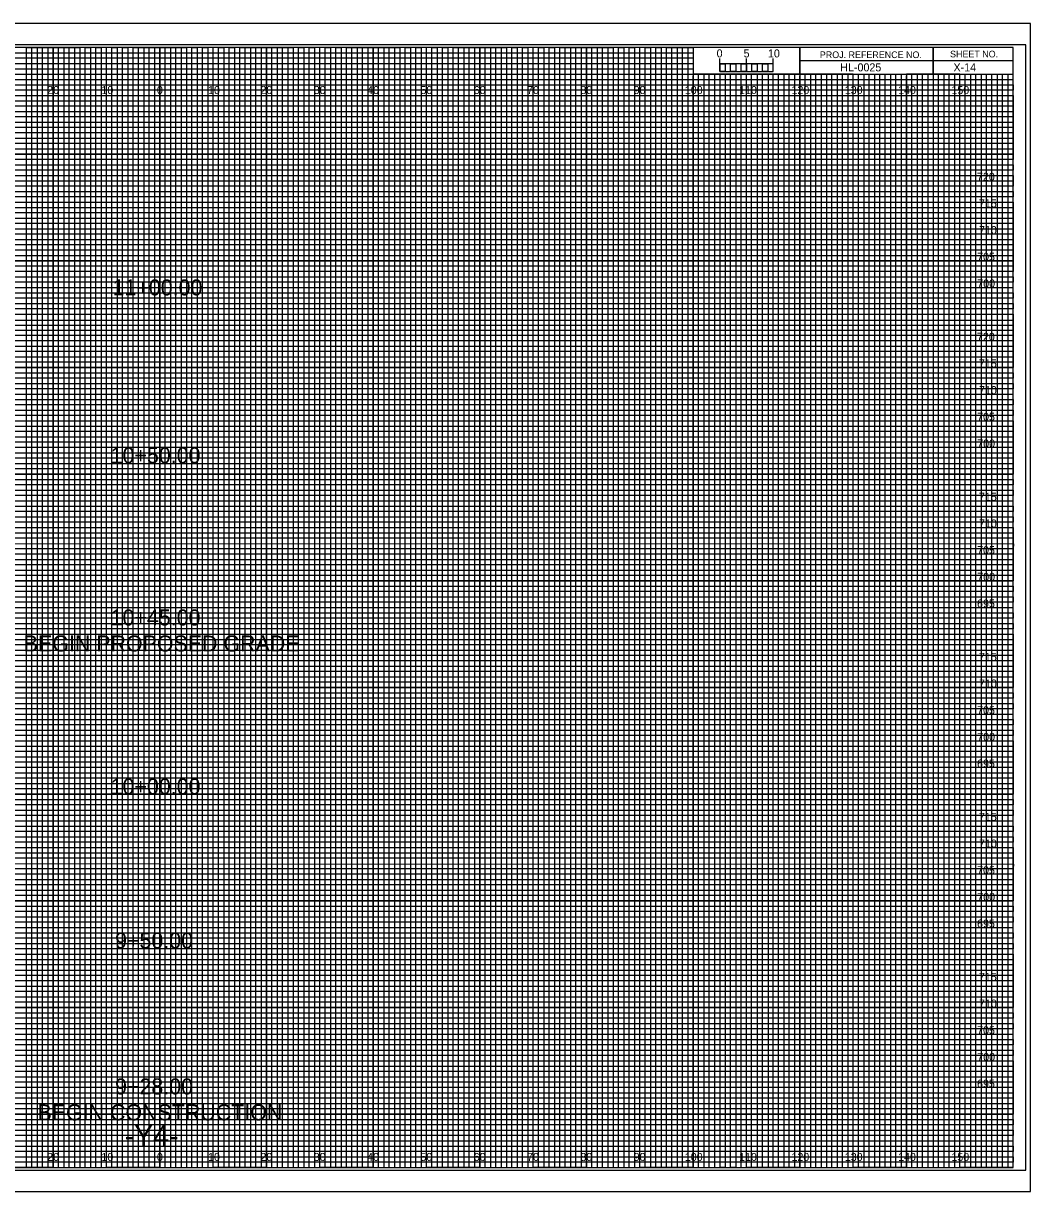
# Model space of a CAD drawing. Extents: x -13 to 323, y -5 to 434.
# Drawn here: x 134.4 to 323.3, y -4.5 to 214.5 of the extents above; entities that cross this region are included whole.
import ezdxf

# ---------------------------------------------------------------- set-up
doc = ezdxf.new("R2010")
doc.units = 0
for name, color, linetype in [('Exist CMT Pavement', 7, 'Continuous'), ('Exist Cross Section Cell', 7, 'Continuous'), ('Exist XS Center Line Elevation Label', 7, 'Continuous'), ('Exist XS Ground Line', 7, 'Continuous'), ('Prop CMT Pvmt Course 1 Wedge', 7, 'Continuous'), ('Prop CMT Pvmt Course 2', 7, 'Continuous'), ('Prop CMT Pvmt Course 3', 7, 'Continuous'), ('Prop CMT Pvmt Surface', 7, 'Continuous'), ('Prop CMT Pvmt Surface Shoulder', 7, 'Continuous'), ('Prop CMT Pvmt Wedge Surface 1', 7, 'Continuous'), ('Prop CMT Pvmt Wedge Surface 2', 7, 'Continuous'), ('Prop CMT Pvmt Wedge Surface 3', 7, 'Continuous'), ('Prop CMT Shld Paved Course 1', 7, 'Continuous'), ('Prop CMT Shld Paved Course 2', 7, 'Continuous'), ('Prop CMT Shld Paved Course 3', 7, 'Continuous'), ('Prop CMT Subgrade Earthwork', 7, 'Continuous'), ('Scratch_Level_1', 7, 'Continuous')]:
    doc.layers.add(name, color=color, linetype=linetype)

msp = doc.modelspace()

# ---------------------------------------------------------------- linework, layer by layer
at = {"layer": 'Exist XS Center Line Elevation Label'}
for points in [[(125, 0), (135, 0), (135, 210), (145, 210), (145, 0), (155, 0), (155, 210), (165, 210), (165, 0), (175, 0), (175, 210), (185, 210), (185, 0), (195, 0), (195, 210), (205, 210), (205, 0), (215, 0), (215, 210), (225, 210), (225, 0), (235, 0), (235, 210), (245, 210), (245, 0), (255, 0), (255, 210), (259.93, 210), (260, 210), (260, 205), (264.99, 205), (264.99, 0), (275, 0), (275, 205), (285, 205), (285, 0), (295, 0), (295, 205), (305, 205), (305, 0), (315, 0), (315, 205)], [(0, 205), (275, 205)], [(0, 185), (320, 185), (320, 195), (0, 195)], [(0, 165), (320, 165), (320, 175), (0, 175)], [(0, 145), (320, 145), (320, 155), (0, 155)], [(0, 125), (320, 125), (320, 135), (0, 135)], [(0, 105), (320, 105), (320, 115), (0, 115)], [(0, 85), (320, 85), (320, 95), (0, 95)], [(0, 65), (320, 65), (320, 75), (0, 75)], [(0, 45), (320, 45), (320, 55), (0, 55)], [(0, 25), (320, 25), (320, 35), (0, 35)], [(0, 5), (320, 5), (320, 15), (0, 15)]]:
    msp.add_lwpolyline(points, dxfattribs=at)
at = {"layer": 'Exist XS Ground Line'}
for p, q in [((150, 210), (140, 210)), ((140, 210), (140, 0)), ((150, 0), (150, 210)), ((170, 210), (160, 210)), ((160, 210), (160, 0)), ((170, 0), (170, 210)), ((190, 210), (180, 210)), ((180, 210), (180, 0)), ((190, 0), (190, 210)), ((210, 210), (200, 210)), ((200, 210), (200, 0)), ((210, 0), (210, 210)), ((230, 210), (220, 210)), ((220, 210), (220, 0)), ((230, 0), (230, 210)), ((250, 210), (240, 210)), ((240, 210), (240, 0)), ((250, 0), (250, 210)), ((260, 210), (260, 0)), ((270, 0), (270, 205)), ((290, 205), (280, 205)), ((280, 205), (280, 0)), ((290, 0), (290, 205)), ((310, 205), (300, 205)), ((300, 205), (300, 0)), ((310, 0), (310, 205)), ((140, 0), (130, 0)), ((160, 0), (150, 0)), ((180, 0), (170, 0)), ((200, 0), (190, 0)), ((220, 0), (210, 0)), ((240, 0), (230, 0)), ((260, 0), (250, 0)), ((280, 0), (270, 0)), ((300, 0), (290, 0)), ((320, 0), (310, 0)), ((320, 0), (320, 0))]:
    msp.add_line(p, q, dxfattribs=at)
for points in [[(0, 200), (320, 200), (320, 190), (0, 190)], [(0, 180), (320, 180), (320, 170), (0, 170)], [(0, 160), (320, 160), (320, 150), (0, 150)], [(0, 140), (320, 140), (320, 130), (0, 130)], [(0, 120), (320, 120), (320, 110), (0, 110)], [(0, 100), (320, 100), (320, 90), (0, 90)], [(0, 80), (320, 80), (320, 70), (0, 70)], [(0, 60), (320, 60), (320, 50), (0, 50)], [(0, 40), (320, 40), (320, 30), (0, 30)], [(0, 20), (320, 20), (320, 10), (0, 10)]]:
    msp.add_lwpolyline(points, dxfattribs=at)
at = {"layer": 'Prop CMT Pvmt Course 1 Wedge'}
for p, q in [((323.3, 214.5), (-13.4, 214.5)), ((-13.4, -4.5), (323.3, -4.5))]:
    msp.add_line(p, q, dxfattribs=at)
at = {"layer": 'Prop CMT Pvmt Course 2'}
msp.add_lwpolyline([(-13.4, -4.5), (323.3, -4.5), (323.3, 214.5), (-13.4, 214.5)], close=True, dxfattribs=at)
at = {"layer": 'Prop CMT Pvmt Course 3'}
msp.add_lwpolyline([(-10.8, -0.5), (322.4, -0.5), (322.4, 210.5), (-10.8, 210.5)], close=True, dxfattribs=at)
at = {"layer": 'Prop CMT Shld Paved Course 1'}
for p, q in [((305, 210), (305, 205)), ((305, 205), (305, 210)), ((280, 207.5), (280, 205)), ((320, 207.49), (280, 207.49)), ((280, 205), (320, 205))]:
    msp.add_line(p, q, dxfattribs=at)
for points in [[(320, 210), (0, 210), (0, 0), (320, 0)], [(280, 210), (260, 210), (260, 205.03), (280, 205.03)], [(320, 210), (280, 210), (280, 205), (320, 205)]]:
    msp.add_lwpolyline(points, close=True, dxfattribs=at)
at = {"layer": 'Prop CMT Shld Paved Course 2'}
for p, q in [((267, 205), (266.01, 205)), ((266.01, 205), (266.01, 0)), ((267, 0), (267, 205)), ((269, 205), (268, 205)), ((268, 205), (268, 0)), ((269, 0), (269, 205)), ((266.01, 0), (265, 0)), ((268, 0), (267, 0))]:
    msp.add_line(p, q, dxfattribs=at)
for points in [[(135, 0), (136, 0), (136, 210), (137, 210), (137, 0)], [(137, 0), (138, 0), (138, 210), (139, 210), (139, 0)], [(140, 0), (141, 0), (141, 210), (142, 210), (142, 0)], [(142, 0), (143, 0), (143, 210), (144, 210), (144, 0)], [(145, 0), (146, 0), (146, 210), (147, 210), (147, 0)], [(147, 0), (148, 0), (148, 210), (149, 210), (149, 0)], [(150, 0), (151, 0), (151, 210), (152, 210), (152, 0)], [(152, 0), (153, 0), (153, 210), (154, 210), (154, 0)], [(155, 0), (156, 0), (156, 210), (157, 210), (157, 0)], [(157, 0), (158, 0), (158, 210), (159, 210), (159, 0)], [(160, 0), (161, 0), (161, 210), (162, 210), (162, 0)], [(162, 0), (163, 0), (163, 210), (164, 210), (164, 0)], [(165, 0), (166, 0), (166, 210), (167, 210), (167, 0)], [(167, 0), (168, 0), (168, 210), (169, 210), (169, 0)], [(170, 0), (171, 0), (171, 210), (172, 210), (172, 0)], [(172, 0), (173, 0), (173, 210), (174, 210), (174, 0)], [(175, 0), (176, 0), (176, 210), (177, 210), (177, 0)], [(177, 0), (178, 0), (178, 210), (179, 210), (179, 0)], [(180, 0), (181, 0), (181, 210), (182, 210), (182, 0)], [(182, 0), (183, 0), (183, 210), (184, 210), (184, 0)], [(185, 0), (186, 0), (186, 210), (187, 210), (187, 0)], [(187, 0), (188, 0), (188, 210), (189, 210), (189, 0)], [(190, 0), (191, 0), (191, 210), (192, 210), (192, 0)], [(192, 0), (193, 0), (193, 210), (194, 210), (194, 0)], [(195, 0), (196, 0), (196, 210), (197, 210), (197, 0)], [(197, 0), (198, 0), (198, 210), (199, 210), (199, 0)], [(200, 0), (201, 0), (201, 210), (202, 210), (202, 0)], [(202, 0), (203, 0), (203, 210), (204, 210), (204, 0)], [(205, 0), (206, 0), (206, 210), (207, 210), (207, 0)], [(207, 0), (208, 0), (208, 210), (209, 210), (209, 0)], [(210, 0), (211, 0), (211, 210), (212, 210), (212, 0)], [(212, 0), (213, 0), (213, 210), (214, 210), (214, 0)], [(215, 0), (216, 0), (216, 210), (217, 210), (217, 0)], [(217, 0), (218, 0), (218, 210), (219, 210), (219, 0)], [(220, 0), (221, 0), (221, 210), (222, 210), (222, 0)], [(222, 0), (223, 0), (223, 210), (224, 210), (224, 0)], [(225, 0), (226, 0), (226, 210), (227, 210), (227, 0)], [(227, 0), (228, 0), (228, 210), (229, 210), (229, 0)], [(230, 0), (231, 0), (231, 210), (232, 210), (232, 0)], [(232, 0), (233, 0), (233, 210), (234, 210), (234, 0)], [(235, 0), (236, 0), (236, 210), (237, 210), (237, 0)], [(237, 0), (238, 0), (238, 210), (239, 210), (239, 0)], [(240, 0), (241, 0), (241, 210), (242, 210), (242, 0)], [(242, 0), (243, 0), (243, 210), (244, 210), (244, 0)], [(245, 0), (246, 0), (246, 210), (247, 210), (247, 0)], [(247, 0), (248, 0), (248, 210), (249, 210), (249, 0)], [(250, 0), (251, 0), (251, 210), (252, 210), (252, 0)], [(252, 0), (253, 0), (253, 210), (254, 210), (254, 0)], [(255, 0), (256, 0), (256, 210), (257, 210), (257, 0)], [(257, 0), (258, 0), (258, 210), (259, 210), (259, 0)], [(260, 0), (261, 0), (261, 205), (262.02, 205), (262.02, 0)], [(262, 0), (263, 0), (263, 205), (263.99, 205), (263.99, 0)], [(270, 0), (270.98, 0), (270.98, 205), (272, 205), (272, 0)], [(272, 0), (273, 0), (273, 205), (274.05, 205), (274.05, 0)], [(275, 0), (276, 0), (276, 205), (277, 205), (277, 0)], [(277, 0), (278, 0), (278, 205), (279, 205), (279, 0)], [(280, 0), (281, 0), (281, 205), (282, 205), (282, 0)], [(282, 0), (283, 0), (283, 205), (284, 205), (284, 0)], [(285, 0), (286, 0), (286, 205), (287, 205), (287, 0)], [(287, 0), (288, 0), (288, 205), (289, 205), (289, 0)], [(290, 0), (291, 0), (291, 205), (292, 205), (292, 0)], [(292, 0), (293, 0), (293, 205), (294, 205), (294, 0)], [(295, 0), (296, 0), (296, 205), (297, 205), (297, 0)], [(297, 0), (298, 0), (298, 205), (299, 205), (299, 0)], [(300, 0), (301, 0), (301, 205), (302, 205), (302, 0)], [(302, 0), (303, 0), (303, 205), (304, 205), (304, 0)], [(305, 0), (306, 0), (306, 205), (307, 205), (307, 0)], [(307, 0), (308, 0), (308, 205), (309, 205), (309, 0)], [(310, 0), (311, 0), (311, 205), (312, 205), (312, 0)], [(312, 0), (313, 0), (313, 205), (314, 205), (314, 0)], [(315, 0), (316, 0), (316, 205), (317, 205), (317, 0)], [(317, 0), (318, 0), (318, 205), (319, 205), (319, 0)]]:
    msp.add_lwpolyline(points, dxfattribs=at)
at = {"layer": 'Prop CMT Shld Paved Course 3'}
for p, q in [((265, 205.49), (265, 207.9)), ((265, 206.9), (265, 207.9)), ((270, 205.49), (270, 207.9)), ((275, 205.49), (275, 207.9)), ((275, 206.9), (275, 207.9))]:
    msp.add_line(p, q, dxfattribs=at)
for points in [[(275, 206.9), (265, 206.9), (265, 205.49), (275, 205.49)], [(265, 206.9), (266, 206.9), (266, 205.49), (265, 205.49)], [(267, 206.9), (268, 206.9), (268, 205.49), (267, 205.49)], [(269, 206.9), (270, 206.9), (270, 205.49), (269, 205.49)], [(271, 206.9), (272, 206.9), (272, 205.49), (271, 205.49)], [(273, 206.9), (274, 206.9), (274, 205.49), (273, 205.49)]]:
    msp.add_lwpolyline(points, close=True, dxfattribs=at)
at = {"layer": 'Prop CMT Subgrade Earthwork'}
for p, q in [((140, 0), (140, 210)), ((150, 0), (150, 210)), ((160, 0), (160, 210)), ((170, 0), (170, 210)), ((180, 0), (180, 210)), ((190, 0), (190, 210)), ((200, 0), (200, 210)), ((210, 0), (210, 210)), ((220, 0), (220, 210)), ((230, 0), (230, 210)), ((240, 0), (240, 210)), ((250, 0), (250, 210)), ((260, 0), (260, 204.69)), ((270, 0), (270, 204.69)), ((280, 0), (280, 204.69)), ((290, 0), (290, 204.69)), ((300, 0), (300, 204.69)), ((310, 0), (310, 204.69)), ((0, 200), (320, 200)), ((0, 190), (320, 190)), ((0, 180), (320, 180)), ((0, 170), (320, 170)), ((0, 160), (320, 160)), ((0, 150), (320, 150)), ((0, 140), (320, 140)), ((0, 130), (320, 130)), ((0, 120), (320, 120)), ((0, 110), (320, 110)), ((0, 100), (320, 100)), ((0, 90), (320, 90)), ((0, 80), (320, 80)), ((0, 70), (320, 70)), ((0, 60), (320, 60)), ((0, 50), (320, 50)), ((0, 40), (320, 40)), ((0, 30), (320, 30)), ((0, 20), (320, 20)), ((0, 10), (320, 10))]:
    msp.add_line(p, q, dxfattribs=at)
at = {"layer": 'Scratch_Level_1'}
for p, q in [((0, 209), (260, 209)), ((260, 209), (260, 207.98)), ((260, 207.98), (0, 207.98)), ((0, 207), (260, 207)), ((260, 205.89), (0, 205.89)), ((260, 207), (260, 205.89)), ((0, 204), (320, 204))]:
    msp.add_line(p, q, dxfattribs=at)
for points in [[(0, 203), (270, 203), (320, 203), (320, 202), (0, 202)], [(0, 201), (320, 201), (320, 199), (0, 199)], [(0, 198), (320, 198), (320, 197), (0, 196.98)], [(0, 196), (320, 196), (320, 194), (0, 194)], [(0, 193), (320, 193), (320, 192), (0, 192)], [(0, 191), (320, 191), (320, 189), (0, 189)], [(0, 188), (320, 188), (320, 187), (0, 187)], [(0, 186), (320, 186), (320, 184), (0, 184)], [(0, 183), (320, 183), (320, 182), (0, 182)], [(0, 181), (320, 181), (320, 179), (0, 179)], [(0, 178), (320, 178), (320, 177), (0, 177)], [(0, 176), (320, 176), (320, 173.95), (320, 173), (320, 172), (0, 172)], [(0, 174), (320, 174), (320, 173), (0, 173)], [(0, 171), (320, 171), (320, 169), (0, 169.03)], [(0, 169.03), (320, 169), (320, 168), (0, 168)], [(0, 167), (320, 167), (320, 166), (0, 166)], [(0, 164), (320, 164), (320, 163), (0, 163)], [(0, 162), (320, 162), (320, 161), (0, 161)], [(-0.07, 158.89), (320, 158.89), (320, 157.88), (-0.07, 157.88)], [(0, 157), (320, 157), (320, 156), (0, 156)], [(0, 154), (320, 154), (320, 153), (0, 153)], [(0, 152), (320, 152), (320, 151), (0, 151)], [(0, 149), (320, 149), (320, 148), (0, 148)], [(0, 147), (320, 147), (320, 146), (0, 146)], [(0, 144), (320, 144), (320, 143), (0, 143)], [(0, 142), (320, 142), (320, 141), (0, 141)], [(0, 139), (320, 139), (319.99, 137.98), (0, 138)], [(0, 137), (320, 137), (320, 136), (0, 136)], [(0, 134), (320, 134), (320, 133), (0, 133)], [(0, 132), (320, 132), (320, 131), (0, 131)], [(0, 129), (320, 129), (320, 128), (0, 128)], [(0, 127), (320, 127), (320, 126), (0, 126)], [(0, 124), (320, 124), (320, 123), (0, 123)], [(0, 122), (320, 122), (320, 121), (0, 121)], [(0, 119), (320, 119), (320, 118), (0, 118)], [(0, 116.99), (320.07, 116.91), (320, 116), (0, 116)], [(0, 114), (320, 114), (320, 113), (0, 113)], [(0, 112), (320, 112), (320, 111), (0, 111)], [(0, 109), (320, 109), (320, 108), (0, 108)], [(0, 107), (320, 107), (320, 106), (0, 106)], [(0, 104), (320, 104), (320, 103), (0, 103)], [(0, 102), (320, 102), (320, 101), (0, 101)], [(0, 99), (320, 99), (320, 98), (0, 98)], [(0, 97), (320, 97), (320, 96), (0, 96)], [(0, 94), (320, 94), (320, 93), (0, 93)], [(0, 92), (320, 92), (320, 91), (0, 91)], [(0, 89), (320, 89), (320, 88), (0, 88)], [(0, 87), (320, 87), (320, 86), (0, 86)], [(0, 84), (320, 84), (320, 83), (0, 83)], [(0, 82), (320, 82), (320, 81), (0, 81)], [(0, 79), (320, 79), (319.99, 77.98), (0, 78)], [(0, 77), (320, 77), (320, 76), (0, 76)], [(0, 74), (320, 74), (320, 73), (0, 73)], [(0, 72), (320, 72), (320, 71), (0, 71)], [(0, 69), (320, 69), (320, 68), (0, 68)], [(0, 67), (320, 67), (320, 66), (0, 66)], [(0, 64), (320, 64), (320, 63), (0, 63)], [(0, 62), (320, 62), (320, 61), (0, 61)], [(0, 59), (320, 59), (320, 58), (0, 58)], [(0, 56.99), (320.07, 56.91), (320, 56), (0, 56)], [(0, 54), (320, 54), (320, 53), (0, 53)], [(0, 52), (320, 52), (320, 51), (0, 51)], [(0, 49), (320, 49), (320, 48), (0, 48)], [(0, 47), (320, 47), (320, 46), (0, 46)], [(0, 44), (320, 44), (320, 43), (0, 43)], [(0, 42), (320, 42), (320, 41), (0, 41)], [(0, 39), (320, 39), (320, 38), (0, 38)], [(0, 37), (320, 37), (320, 36), (0, 36)], [(0, 34), (320, 34), (320, 33), (0, 33)], [(0, 32), (320, 32), (320, 31), (0, 31)], [(0, 29), (320, 29), (320, 28), (0, 28)], [(0, 27), (320, 27), (320, 26), (0, 26)], [(0, 24), (320, 24), (320, 23), (0, 23)], [(0, 22), (320, 22), (320, 21), (0, 21)], [(0, 19), (320, 19), (320, 18), (0, 18)], [(0, 17), (320, 17), (320, 16), (0, 16)], [(0, 14), (320, 14), (320, 13), (0, 13)], [(0, 12), (320, 12), (320, 11), (0, 11)], [(0, 9), (320, 9), (320, 8), (0, 8)], [(0, 7), (320, 7), (320, 6), (0, 6)], [(0, 4), (320, 4), (320, 3), (0, 3)], [(0, 2), (320, 2), (320, 1), (0, 1)]]:
    msp.add_lwpolyline(points, dxfattribs=at)

# ---------------------------------------------------------------- texts
at = {"layer": 'Exist CMT Pavement'}
for s, p in [('720', (313.23, 185)), ('715', (313.59, 180)), ('710', (313.61, 175)), ('705', (313.26, 170)), ('700', (313.28, 165)), ('720', (313.23, 155)), ('715', (313.59, 150)), ('710', (313.61, 145)), ('705', (313.26, 140)), ('700', (313.28, 135)), ('715', (313.59, 125)), ('710', (313.61, 120)), ('705', (313.26, 115)), ('700', (313.28, 110)), ('695', (313.25, 105)), ('715', (313.59, 95)), ('710', (313.61, 90)), ('705', (313.26, 85)), ('700', (313.28, 80)), ('695', (313.25, 75)), ('715', (313.59, 65)), ('710', (313.61, 60)), ('705', (313.26, 55)), ('700', (313.28, 50)), ('695', (313.25, 45)), ('715', (313.59, 35)), ('710', (313.61, 30)), ('705', (313.26, 25)), ('700', (313.28, 20)), ('695', (313.25, 15))]:
    msp.add_text(s, height=1.5, dxfattribs=at).set_placement(p)
at = {"layer": 'Exist Cross Section Cell'}
for s, p in [('20', (138.86, 201.25)), ('10', (149.04, 201.25)), ('0', (159.45, 201.25)), ('0', (159.45, 201.25)), ('10', (169.04, 201.25)), ('20', (178.86, 201.25)), ('30', (188.86, 201.25)), ('40', (198.86, 201.25)), ('50', (208.86, 201.25)), ('60', (218.86, 201.25)), ('70', (228.86, 201.25)), ('80', (238.86, 201.25)), ('90', (248.86, 201.25)), ('100', (258.44, 201.25)), ('110', (268.62, 201.25)), ('120', (278.44, 201.25)), ('130', (288.44, 201.25)), ('140', (298.44, 201.25)), ('150', (308.44, 201.25)), ('20', (138.86, 1.25)), ('10', (149.04, 1.25)), ('0', (159.45, 1.25)), ('0', (159.45, 1.25)), ('10', (169.04, 1.25)), ('20', (178.86, 1.25)), ('30', (188.86, 1.25)), ('40', (198.86, 1.25)), ('50', (208.86, 1.25)), ('60', (218.86, 1.25)), ('70', (228.86, 1.25)), ('80', (238.86, 1.25)), ('90', (248.86, 1.25)), ('100', (258.44, 1.25)), ('110', (268.62, 1.25)), ('120', (278.44, 1.25)), ('130', (288.44, 1.25)), ('140', (298.44, 1.25)), ('150', (308.44, 1.25))]:
    msp.add_text(s, height=1.5, dxfattribs=at).set_placement(p)
at = {"layer": 'Prop CMT Pvmt Surface'}
for s, p in [('11+00.00', (151.13, 163.5)), ('10+50.00', (150.77, 132.03)), ('10+45.00', (150.77, 101.63)), ('BEGIN PROPOSED GRADE', (134.47, 96.76)), ('10+00.00', (150.77, 69.96)), ('9+50.00', (151.6, 41.08)), ('9+28.00', (151.6, 13.72)), ('BEGIN CONSTRUCTION', (137.05, 8.85))]:
    msp.add_text(s, height=3, dxfattribs=at).set_placement(p)
at = {"layer": 'Prop CMT Pvmt Surface Shoulder'}
for s, p in [('5', (269.47, 208.12)), ('10', (274.04, 208.12))]:
    msp.add_text(s, height=1.5, dxfattribs=at).set_placement(p)
at = {"layer": 'Prop CMT Pvmt Wedge Surface 1'}
msp.add_text('X-14', height=1.5, dxfattribs=at).set_placement((308.83, 205.5))
at = {"layer": 'Prop CMT Pvmt Wedge Surface 2'}
msp.add_text('HL-0025', height=1.5, dxfattribs=at).set_placement((287.6, 205.5))
at = {"layer": 'Prop CMT Pvmt Wedge Surface 3'}
msp.add_text('-Y4-', height=4, dxfattribs=at).set_placement((153.39, 4))
at = {"layer": 'Prop CMT Shld Paved Course 1'}
for s, p in [('PROJ. REFERENCE NO.', (283.77, 207.99)), ('SHEET NO.', (308.19, 208.12))]:
    msp.add_text(s, height=1.25, dxfattribs=at).set_placement(p)
at = {"layer": 'Prop CMT Shld Paved Course 3'}
msp.add_text('0', height=1.5, dxfattribs=at).set_placement((264.41, 208.12))

doc.saveas('drawing.dxf')
